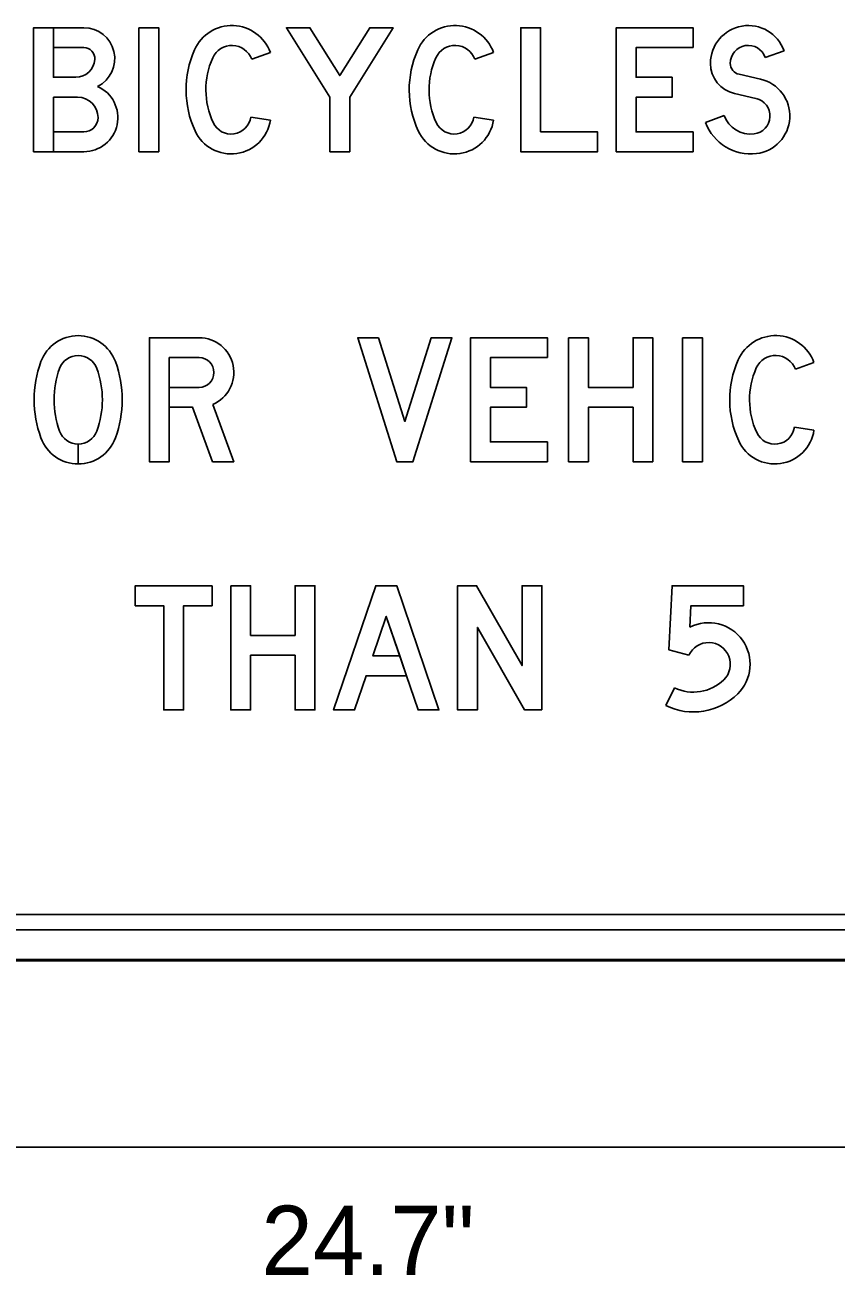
# Model space of a CAD drawing. Extents: x 0 to 770, y 0 to 495.
# Drawn here: x 653.1 to 694.1, y 198.8 to 261.9 of the extents above; entities that cross this region are included whole.
import ezdxf

# ---------------------------------------------------------------- set-up
doc = ezdxf.new("R2010")
doc.units = 0
for name, color, linetype in [('Default', 7, 'Continuous'), ('GSBWFill', 7, 'Continuous'), ('GSColorFill', 7, 'Continuous'), ('GSDims', 7, 'Continuous'), ('GSOutline', 7, 'Continuous')]:
    doc.layers.add(name, color=color, linetype=linetype)

msp = doc.modelspace()

# ---------------------------------------------------------------- linework, layer by layer
at = {"layer": 'Default'}
for p, q in [((656.112, 260.785), (654.578, 260.785)), ((665.535, 260.538), (664.593, 260.195)), ((665.535, 260.538), (664.593, 260.195)), ((665.535, 260.538), (664.593, 260.195)), ((676.804, 260.538), (675.863, 260.195)), ((676.804, 260.538), (675.863, 260.195)), ((676.804, 260.538), (675.863, 260.195)), ((690.528, 260.285), (691.474, 260.613)), ((690.528, 260.285), (691.474, 260.613)), ((690.528, 260.285), (691.474, 260.613)), ((690.281, 259.192), (689.201, 259.437)), ((690.281, 259.192), (689.201, 259.437)), ((690.281, 259.192), (689.201, 259.437)), ((654.578, 258.281), (655.799, 258.281)), ((654.578, 258.281), (655.799, 258.281)), ((654.578, 258.281), (655.799, 258.281)), ((688.979, 258.461), (690.059, 258.215)), ((688.979, 258.461), (690.059, 258.215)), ((688.979, 258.461), (690.059, 258.215)), ((664.544, 257.272), (665.535, 257.124)), ((664.544, 257.272), (665.535, 257.124)), ((664.544, 257.272), (665.535, 257.124)), ((675.813, 257.272), (676.804, 257.124)), ((675.813, 257.272), (676.804, 257.124)), ((675.813, 257.272), (676.804, 257.124)), ((688.448, 257.351), (687.51, 256.997)), ((688.448, 257.351), (687.51, 256.997)), ((688.448, 257.351), (687.51, 256.997)), ((653.576, 255.526), (656.112, 255.526)), ((660.432, 245.133), (661.935, 245.133)), ((660.432, 245.133), (661.935, 245.133)), ((692.988, 244.886), (692.047, 244.543)), ((692.988, 244.886), (692.047, 244.543)), ((692.988, 244.886), (692.047, 244.543)), ((663.688, 239.874), (662.623, 242.77)), ((691.998, 241.62), (692.988, 241.472)), ((691.998, 241.62), (692.988, 241.472)), ((691.998, 241.62), (692.988, 241.472)), ((655.83, 240.766), (655.83, 239.764)), ((655.83, 240.766), (655.83, 239.764)), ((655.831, 239.764), (655.831, 240.766)), ((655.831, 239.764), (655.831, 240.766)), ((685.507, 227.563), (685.944, 228.464)), ((685.507, 227.563), (685.944, 228.464)), ((685.507, 227.563), (685.944, 228.464)), ((685.944, 228.464), (685.944, 228.464)), ((685.944, 228.464), (685.944, 228.464)), ((685.944, 228.464), (685.944, 228.464))]:
    msp.add_line(p, q, dxfattribs=at)
for points in [[(656.112, 261.787), (653.576, 261.787), (653.576, 255.526)], [(655.706, 259.283), (654.578, 259.283), (654.578, 261.787), (653.576, 261.787), (653.576, 255.526), (654.578, 255.526), (654.578, 258.281)], [(655.706, 259.283), (654.578, 259.283), (654.578, 261.787), (653.576, 261.787), (653.576, 255.526), (654.578, 255.526), (654.578, 258.281)], [(656.112, 261.787), (654.578, 261.787), (654.578, 260.785), (656.112, 260.785)], [(656.112, 261.787), (654.578, 261.787), (654.578, 260.785), (656.112, 260.785)], [(654.578, 260.785), (654.578, 259.283), (655.706, 259.283)], [(656.112, 256.528), (654.578, 256.528), (654.578, 258.281)], [(656.112, 256.528), (654.578, 256.528), (654.578, 255.526), (656.112, 255.526)], [(656.112, 256.528), (654.578, 256.528), (654.578, 255.526), (656.112, 255.526)], [(661.935, 246.135), (659.43, 246.135), (659.43, 239.874), (660.432, 239.874), (660.432, 242.629), (661.608, 242.629), (662.62, 239.874), (663.688, 239.874)], [(661.935, 246.135), (659.43, 246.135), (659.43, 239.874), (660.432, 239.874), (660.432, 245.133)], [(661.935, 246.135), (659.43, 246.135), (659.43, 239.874), (660.432, 239.874), (660.432, 245.133)], [(661.935, 243.63), (660.432, 243.63), (660.432, 245.133), (661.935, 245.133)], [(661.935, 243.63), (660.432, 243.63), (660.432, 242.629), (661.608, 242.629), (662.62, 239.874), (663.688, 239.874), (662.623, 242.77)], [(661.935, 243.63), (660.432, 243.63), (660.432, 242.629), (661.608, 242.629), (662.62, 239.874), (663.688, 239.874), (662.623, 242.77)], [(686.669, 230.107), (685.663, 230.389), (685.82, 233.613), (689.42, 233.613), (689.42, 232.611), (686.774, 232.611), (686.721, 231.525)], [(686.669, 230.107), (685.663, 230.389), (685.82, 233.613), (689.42, 233.613), (689.42, 232.611), (686.774, 232.611), (686.721, 231.525)], [(686.669, 230.107), (685.663, 230.389), (685.82, 233.613), (689.42, 233.613), (689.42, 232.611), (686.774, 232.611), (686.721, 231.525)]]:
    msp.add_lwpolyline(points, dxfattribs=at)
for points in [[(658.898, 261.787), (659.9, 261.787), (659.9, 255.526), (658.898, 255.526)], [(658.898, 261.787), (659.9, 261.787), (659.9, 255.526), (658.898, 255.526)], [(658.898, 261.787), (659.9, 261.787), (659.9, 255.526), (658.898, 255.526)], [(668.54, 255.526), (669.541, 255.526), (669.541, 258.281), (671.733, 261.787), (670.551, 261.787), (669.041, 259.37), (667.53, 261.787), (666.348, 261.787), (668.54, 258.281)], [(668.54, 255.526), (669.541, 255.526), (669.541, 258.281), (671.733, 261.787), (670.551, 261.787), (669.041, 259.37), (667.53, 261.787), (666.348, 261.787), (668.54, 258.281)], [(668.54, 255.526), (669.541, 255.526), (669.541, 258.281), (671.733, 261.787), (670.551, 261.787), (669.041, 259.37), (667.53, 261.787), (666.348, 261.787), (668.54, 258.281)], [(679.183, 256.528), (682.063, 256.528), (682.063, 255.526), (678.181, 255.526), (678.181, 261.787), (679.183, 261.787)], [(679.183, 256.528), (682.063, 256.528), (682.063, 255.526), (678.181, 255.526), (678.181, 261.787), (679.183, 261.787)], [(679.183, 256.528), (682.063, 256.528), (682.063, 255.526), (678.181, 255.526), (678.181, 261.787), (679.183, 261.787)], [(686.884, 260.785), (684.004, 260.785), (684.004, 259.283), (685.825, 259.283), (685.825, 258.281), (684.004, 258.281), (684.004, 256.528), (686.884, 256.528), (686.884, 255.526), (683.002, 255.526), (683.002, 261.787), (686.884, 261.787)], [(686.884, 260.785), (684.004, 260.785), (684.004, 259.283), (685.825, 259.283), (685.825, 258.281), (684.004, 258.281), (684.004, 256.528), (686.884, 256.528), (686.884, 255.526), (683.002, 255.526), (683.002, 261.787), (686.884, 261.787)], [(686.884, 260.785), (684.004, 260.785), (684.004, 259.283), (685.825, 259.283), (685.825, 258.281), (684.004, 258.281), (684.004, 256.528), (686.884, 256.528), (686.884, 255.526), (683.002, 255.526), (683.002, 261.787), (686.884, 261.787)], [(670.999, 246.135), (672.328, 241.916), (673.656, 246.135), (674.707, 246.135), (672.735, 239.874), (671.921, 239.874), (669.948, 246.135)], [(670.999, 246.135), (672.328, 241.916), (673.656, 246.135), (674.707, 246.135), (672.735, 239.874), (671.921, 239.874), (669.948, 246.135)], [(670.999, 246.135), (672.328, 241.916), (673.656, 246.135), (674.707, 246.135), (672.735, 239.874), (671.921, 239.874), (669.948, 246.135)], [(679.528, 245.133), (676.648, 245.133), (676.648, 243.63), (678.468, 243.63), (678.468, 242.629), (676.648, 242.629), (676.648, 240.876), (679.528, 240.876), (679.528, 239.874), (675.646, 239.874), (675.646, 246.135), (679.528, 246.135)], [(679.528, 245.133), (676.648, 245.133), (676.648, 243.63), (678.468, 243.63), (678.468, 242.629), (676.648, 242.629), (676.648, 240.876), (679.528, 240.876), (679.528, 239.874), (675.646, 239.874), (675.646, 246.135), (679.528, 246.135)], [(679.528, 245.133), (676.648, 245.133), (676.648, 243.63), (678.468, 243.63), (678.468, 242.629), (676.648, 242.629), (676.648, 240.876), (679.528, 240.876), (679.528, 239.874), (675.646, 239.874), (675.646, 246.135), (679.528, 246.135)], [(680.592, 246.135), (681.594, 246.135), (681.594, 243.63), (683.848, 243.63), (683.848, 246.135), (684.849, 246.135), (684.849, 239.874), (683.848, 239.874), (683.848, 242.629), (681.594, 242.629), (681.594, 239.874), (680.592, 239.874)], [(680.592, 246.135), (681.594, 246.135), (681.594, 243.63), (683.848, 243.63), (683.848, 246.135), (684.849, 246.135), (684.849, 239.874), (683.848, 239.874), (683.848, 242.629), (681.594, 242.629), (681.594, 239.874), (680.592, 239.874)], [(680.592, 246.135), (681.594, 246.135), (681.594, 243.63), (683.848, 243.63), (683.848, 246.135), (684.849, 246.135), (684.849, 239.874), (683.848, 239.874), (683.848, 242.629), (681.594, 242.629), (681.594, 239.874), (680.592, 239.874)], [(686.352, 246.135), (687.354, 246.135), (687.354, 239.874), (686.352, 239.874)], [(686.352, 246.135), (687.354, 246.135), (687.354, 239.874), (686.352, 239.874)], [(686.352, 246.135), (687.354, 246.135), (687.354, 239.874), (686.352, 239.874)], [(662.592, 233.613), (662.592, 232.611), (661.152, 232.611), (661.152, 227.352), (660.15, 227.352), (660.15, 232.611), (658.71, 232.611), (658.71, 233.613)], [(662.592, 233.613), (662.592, 232.611), (661.152, 232.611), (661.152, 227.352), (660.15, 227.352), (660.15, 232.611), (658.71, 232.611), (658.71, 233.613)], [(662.592, 233.613), (662.592, 232.611), (661.152, 232.611), (661.152, 227.352), (660.15, 227.352), (660.15, 232.611), (658.71, 232.611), (658.71, 233.613)], [(663.531, 233.613), (664.533, 233.613), (664.533, 231.109), (666.787, 231.109), (666.787, 233.613), (667.788, 233.613), (667.788, 227.352), (666.787, 227.352), (666.787, 230.107), (664.533, 230.107), (664.533, 227.352), (663.531, 227.352)], [(663.531, 233.613), (664.533, 233.613), (664.533, 231.109), (666.787, 231.109), (666.787, 233.613), (667.788, 233.613), (667.788, 227.352), (666.787, 227.352), (666.787, 230.107), (664.533, 230.107), (664.533, 227.352), (663.531, 227.352)], [(663.531, 233.613), (664.533, 233.613), (664.533, 231.109), (666.787, 231.109), (666.787, 233.613), (667.788, 233.613), (667.788, 227.352), (666.787, 227.352), (666.787, 230.107), (664.533, 230.107), (664.533, 227.352), (663.531, 227.352)], [(670.371, 229.073), (669.786, 227.352), (668.728, 227.352), (670.856, 233.613), (671.921, 233.613), (674.049, 227.352), (672.991, 227.352), (672.406, 229.073)], [(668.728, 227.352), (670.856, 233.613), (671.921, 233.613), (674.049, 227.352), (672.991, 227.352), (671.388, 232.066), (670.711, 230.075), (672.065, 230.075), (672.406, 229.073), (670.371, 229.073), (669.786, 227.352)], [(668.728, 227.352), (670.856, 233.613), (671.921, 233.613), (674.049, 227.352), (672.991, 227.352), (671.388, 232.066), (670.711, 230.075), (672.065, 230.075), (672.406, 229.073), (670.371, 229.073), (669.786, 227.352)], [(679.246, 227.352), (679.246, 233.613), (678.244, 233.613), (678.244, 229.59), (675.945, 233.613), (674.988, 233.613), (674.988, 227.352), (675.99, 227.352), (675.99, 231.516), (678.369, 227.352)], [(679.246, 227.352), (679.246, 233.613), (678.244, 233.613), (678.244, 229.59), (675.945, 233.613), (674.988, 233.613), (674.988, 227.352), (675.99, 227.352), (675.99, 231.516), (678.369, 227.352)], [(679.246, 227.352), (679.246, 233.613), (678.244, 233.613), (678.244, 229.59), (675.945, 233.613), (674.988, 233.613), (674.988, 227.352), (675.99, 227.352), (675.99, 231.516), (678.369, 227.352)], [(670.711, 230.075), (672.065, 230.075), (671.388, 232.066)]]:
    msp.add_lwpolyline(points, close=True, dxfattribs=at)
for centre, radius, start, end in [((689.67, 259.987), 1.91, 19.13948, 180), ((689.67, 259.987), 1.91, 19.13948, 180), ((689.67, 259.987), 1.91, 19.13948, 180), ((689.67, 259.987), 0.908, 19.13948, 180), ((689.67, 259.987), 0.908, 19.13948, 180), ((689.67, 259.987), 0.908, 19.13948, 180), ((689.326, 259.987), 1.565, 180, 257.19149), ((689.326, 259.987), 1.565, 180, 257.19149), ((689.326, 259.987), 1.565, 180, 257.19149), ((689.326, 259.987), 0.563, 180, 257.19149), ((689.326, 259.987), 0.563, 180, 257.19149), ((689.326, 259.987), 0.563, 180, 257.19149), ((689.858, 257.33), 1.91, 276.78539, 77.19149), ((689.858, 257.33), 1.91, 276.78539, 77.19149), ((689.858, 257.33), 1.91, 276.78539, 77.19149), ((689.858, 257.33), 0.908, 276.78539, 77.19149), ((689.858, 257.33), 0.908, 276.78539, 77.19149), ((689.858, 257.33), 0.908, 276.78539, 77.19149), ((689.795, 257.858), 2.442, 200.64423, 276.78539), ((689.795, 257.858), 2.442, 200.64423, 276.78539), ((689.795, 257.858), 2.442, 200.64423, 276.78539), ((689.795, 257.858), 1.44, 200.64423, 276.78539), ((689.795, 257.858), 1.44, 200.64423, 276.78539), ((689.795, 257.858), 1.44, 200.64423, 276.78539), ((661.935, 244.382), 1.753, 293.1324, 90), ((661.935, 244.382), 1.753, 293.1324, 90), ((661.935, 244.382), 1.753, 293.1324, 90), ((661.935, 244.382), 0.751, 270, 90), ((661.935, 244.382), 0.751, 270, 90), ((661.935, 244.382), 0.751, 270, 90)]:
    msp.add_arc(centre, radius, start, end, dxfattribs=at)
for centre, major_axis, start_param, end_param in [((663.593, 259.83), (0, 2.066), 5.061866, 7.434148), ((663.593, 259.83), (0, 2.066), 5.061866, 7.434148), ((663.593, 259.83), (0, 2.066), 5.061866, 7.434148), ((674.863, 259.83), (0, 2.066), 5.061866, 7.434148), ((674.863, 259.83), (0, 2.066), 5.061866, 7.434148), ((674.863, 259.83), (0, 2.066), 5.061866, 7.434148), ((656.112, 260.222), (1.565, 0), 5.175344, 7.853982), ((656.112, 260.222), (1.565, 0), 5.175344, 7.853982), ((656.112, 260.222), (1.565, 0), 5.175344, 7.853982), ((656.112, 260.222), (0.563, 0), 6.206186, 7.853982), ((656.112, 260.222), (0.563, 0), 6.206186, 7.853982), ((656.112, 260.222), (0.563, 0), 6.206186, 7.853982), ((666.223, 258.656), (0, 4.946), 1.150963, 2.004476), ((666.223, 258.656), (0, 4.946), 1.150963, 2.004476), ((666.223, 258.656), (0, 4.946), 1.150963, 2.004476), ((663.593, 259.83), (0, 1.064), 5.061866, 7.434148), ((663.593, 259.83), (0, 1.064), 5.061866, 7.434148), ((663.593, 259.83), (0, 1.064), 5.061866, 7.434148), ((677.493, 258.656), (0, 4.946), 1.150963, 2.004476), ((677.493, 258.656), (0, 4.946), 1.150963, 2.004476), ((677.493, 258.656), (0, 4.946), 1.150963, 2.004476), ((674.863, 259.83), (0, 1.064), 5.061866, 7.434148), ((674.863, 259.83), (0, 1.064), 5.061866, 7.434148), ((674.863, 259.83), (0, 1.064), 5.061866, 7.434148), ((655.706, 260.253), (0.97, 0), 4.712389, 6.206186), ((655.706, 260.253), (0.97, 0), 4.712389, 6.206186), ((655.706, 260.253), (0.97, 0), 4.712389, 6.206186), ((666.223, 258.656), (0, 3.944), 1.150963, 2.004476), ((666.223, 258.656), (0, 3.944), 1.150963, 2.004476), ((666.223, 258.656), (0, 3.944), 1.150963, 2.004476), ((677.493, 258.656), (0, 3.944), 1.150963, 2.004476), ((677.493, 258.656), (0, 3.944), 1.150963, 2.004476), ((677.493, 258.656), (0, 3.944), 1.150963, 2.004476), ((656.112, 257.248), (1.722, 0), 4.712389, 7.435915), ((656.112, 257.248), (1.722, 0), 4.712389, 7.435915), ((656.112, 257.248), (1.722, 0), 4.712389, 7.435915), ((655.799, 257.248), (1.033, 0), 0, 1.570796), ((655.799, 257.248), (1.033, 0), 0, 1.570796), ((655.799, 257.248), (1.033, 0), 0, 1.570796), ((656.112, 257.248), (0.72, 0), 4.712389, 6.283185), ((656.112, 257.248), (0.72, 0), 4.712389, 6.283185), ((656.112, 257.248), (0.72, 0), 4.712389, 6.283185), ((663.553, 257.42), (0, 2.003), 2.004476, 4.564141), ((663.553, 257.42), (0, 2.003), 2.004476, 4.564141), ((663.553, 257.42), (0, 2.003), 2.004476, 4.564141), ((663.553, 257.42), (0, 1.002), 2.004476, 4.564141), ((663.553, 257.42), (0, 1.002), 2.004476, 4.564141), ((663.553, 257.42), (0, 1.002), 2.004476, 4.564141), ((674.823, 257.42), (0, 2.003), 2.004476, 4.564141), ((674.823, 257.42), (0, 2.003), 2.004476, 4.564141), ((674.823, 257.42), (0, 2.003), 2.004476, 4.564141), ((674.823, 257.42), (0, 1.002), 2.004476, 4.564141), ((674.823, 257.42), (0, 1.002), 2.004476, 4.564141), ((674.823, 257.42), (0, 1.002), 2.004476, 4.564141), ((655.83, 244.241), (0, 2.003), 5.063177, 7.503193), ((655.83, 244.241), (0, 2.003), 5.063177, 7.503193), ((655.83, 244.241), (0, 2.003), 5.063177, 7.503193), ((691.047, 244.178), (0, 2.066), 5.061866, 7.434148), ((691.047, 244.178), (0, 2.066), 5.061866, 7.434148), ((691.047, 244.178), (0, 2.066), 5.061866, 7.434148), ((659.209, 243.004), (0, 5.602), 1.220008, 1.921585), ((659.209, 243.004), (0, 5.602), 1.220008, 1.921585), ((659.209, 243.004), (0, 5.602), 1.220008, 1.921585), ((655.83, 244.241), (0, 1.002), 5.063177, 7.503193), ((655.83, 244.241), (0, 1.002), 5.063177, 7.503193), ((655.83, 244.241), (0, 1.002), 5.063177, 7.503193), ((652.451, 243.004), (0, 5.602), 4.361601, 5.063177), ((652.451, 243.004), (0, 5.602), 4.361601, 5.063177), ((652.451, 243.004), (0, 5.602), 4.361601, 5.063177), ((693.677, 243.004), (0, 4.946), 1.150963, 2.004476), ((693.677, 243.004), (0, 4.946), 1.150963, 2.004476), ((693.677, 243.004), (0, 4.946), 1.150963, 2.004476), ((691.047, 244.178), (0, 1.064), 5.061866, 7.434148), ((691.047, 244.178), (0, 1.064), 5.061866, 7.434148), ((691.047, 244.178), (0, 1.064), 5.061866, 7.434148), ((659.209, 243.004), (0, 4.6), 1.220008, 1.921585), ((659.209, 243.004), (0, 4.6), 1.220008, 1.921585), ((659.209, 243.004), (0, 4.6), 1.220008, 1.921585), ((652.451, 243.004), (0, 4.6), 4.361601, 5.063177), ((652.451, 243.004), (0, 4.6), 4.361601, 5.063177), ((652.451, 243.004), (0, 4.6), 4.361601, 5.063177), ((693.677, 243.004), (0, 3.944), 1.150963, 2.004476), ((693.677, 243.004), (0, 3.944), 1.150963, 2.004476), ((693.677, 243.004), (0, 3.944), 1.150963, 2.004476), ((655.83, 241.768), (0, 2.003), 1.921585, 4.361601), ((655.83, 241.768), (0, 2.003), 1.921585, 3.141593), ((655.83, 241.768), (0, 2.003), 1.921585, 3.141593), ((655.83, 241.768), (0, 1.002), 1.921585, 4.361601), ((655.83, 241.768), (0, 1.002), 1.921585, 3.141593), ((655.83, 241.768), (0, 1.002), 1.921585, 3.141593), ((655.83, 241.768), (0, 1.002), 3.141905, 4.361601), ((655.83, 241.768), (0, 1.002), 3.141905, 4.361601), ((655.83, 241.768), (0, 2.003), 3.141749, 4.361601), ((655.83, 241.768), (0, 2.003), 3.141749, 4.361601), ((691.007, 241.768), (0, 2.003), 2.004476, 4.564141), ((691.007, 241.768), (0, 2.003), 2.004476, 4.564141), ((691.007, 241.768), (0, 2.003), 2.004476, 4.564141), ((691.007, 241.768), (0, 1.002), 2.004476, 4.564141), ((691.007, 241.768), (0, 1.002), 2.004476, 4.564141), ((691.007, 241.768), (0, 1.002), 2.004476, 4.564141), ((687.667, 229.653), (0, 2.097), 3.916786, 6.750783), ((687.667, 229.653), (0, 2.097), 3.916786, 6.750783), ((687.667, 229.653), (0, 2.097), 3.916786, 6.750783), ((687.667, 229.653), (0, 1.096), 3.916786, 7.426824), ((687.667, 229.653), (0, 1.096), 3.916786, 7.426824), ((687.667, 229.653), (0, 1.096), 3.916786, 7.426824), ((686.9, 230.436), (0, 2.191), 2.690083, 3.916786), ((686.9, 230.436), (0, 2.191), 2.690083, 3.916786), ((686.9, 230.436), (0, 2.191), 2.690083, 3.916786), ((686.9, 230.436), (0, 3.193), 2.690083, 3.916786), ((686.9, 230.436), (0, 3.193), 2.690083, 3.916786), ((686.9, 230.436), (0, 3.193), 2.690083, 3.916786)]:
    msp.add_ellipse(centre, major_axis=major_axis, ratio=0.999993, start_param=start_param, end_param=end_param, dxfattribs=at)
at = {"layer": 'GSBWFill'}
for p, q in [((705.541, 217.022), (639.81, 217.022)), ((639.81, 216.239), (705.541, 216.239)), ((639.802, 214.674), (705.541, 214.674))]:
    msp.add_line(p, q, dxfattribs=at)
at = {"layer": 'GSColorFill'}
for p, q in [((705.541, 217.022), (639.81, 217.022)), ((639.81, 216.239), (705.541, 216.239)), ((639.802, 214.674), (705.541, 214.674)), ((705.541, 214.752), (639.803, 214.752)), ((639.803, 214.674), (705.541, 214.674))]:
    msp.add_line(p, q, dxfattribs=at)
at = {"layer": 'GSDims'}
msp.add_line((633.98, 205.283), (711.364, 205.283), dxfattribs=at)
at = {"layer": 'GSOutline'}
for p, q in [((639.802, 217.022), (705.541, 217.022)), ((639.802, 216.239), (705.541, 216.239)), ((639.802, 214.674), (705.541, 214.674))]:
    msp.add_line(p, q, dxfattribs=at)

# ---------------------------------------------------------------- texts
at = {"layer": 'Default'}
msp.add_text('24.7"', height=3.5, dxfattribs=at).set_placement((665.078, 198.821))

doc.saveas('drawing.dxf')
